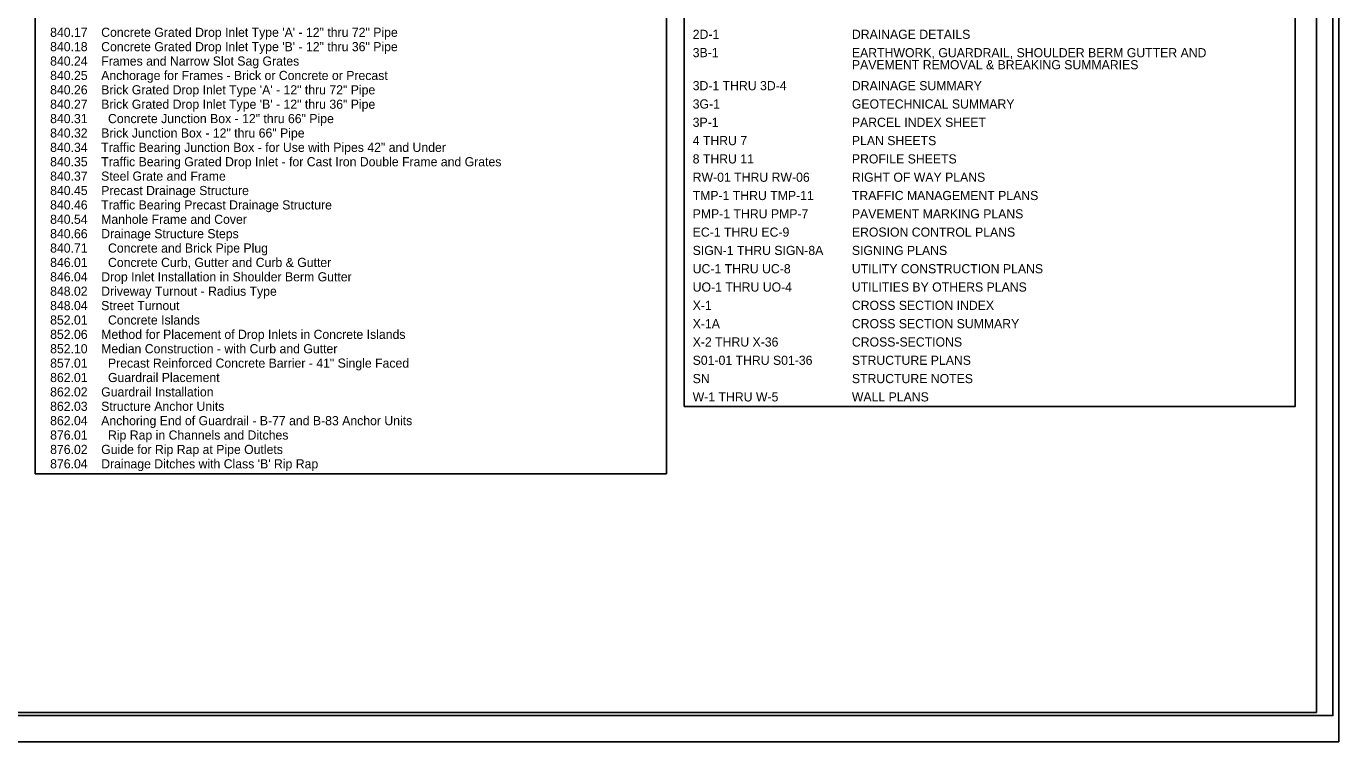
# Model space of a CAD drawing. Extents: x 93723152 to 93807327, y 70087853 to 70142603.
# Drawn here: x 93757166 to 93807327, y 70087853 to 70115212 of the extents above; entities that cross this region are included whole.
import ezdxf

# ---------------------------------------------------------------- set-up
doc = ezdxf.new("R2010")
doc.units = 0
for name, color, linetype in [('Default', 7, 'Continuous'), ('Old_Level_1', 7, 'Continuous'), ('Sheet Cutting Line CELL', 7, 'Continuous'), ('Sheet Plan CELL', 7, 'Continuous'), ('Sheet Plot Border Inside CELL', 7, 'Continuous'), ('Sheet Plot Border Outside CELL', 7, 'Continuous')]:
    doc.layers.add(name, color=color, linetype=linetype)

msp = doc.modelspace()

# ---------------------------------------------------------------- linework, layer by layer
at = {"layer": 'Old_Level_1'}
for points in [[(93757503, 70098101), (93781631, 70098101), (93781631, 70138611), (93757503, 70138611)], [(93782306, 70100674), (93805663, 70100674), (93805663, 70125470), (93782306, 70125470)]]:
    msp.add_lwpolyline(points, close=True, dxfattribs=at)
at = {"layer": 'Sheet Cutting Line CELL'}
msp.add_line((93723152, 70087853), (93807327, 70087853), dxfattribs=at)
at = {"layer": 'Sheet Plan CELL'}
for points in [[(93731477, 70088977), (93731476, 70141476), (93796475, 70141478), (93796476, 70133975), (93806477, 70133974), (93806477, 70088977)], [(93806477, 70141478), (93731477, 70141478), (93731477, 70088978), (93806477, 70088978)]]:
    msp.add_lwpolyline(points, close=True, dxfattribs=at)
at = {"layer": 'Sheet Plot Border Inside CELL'}
msp.add_lwpolyline([(93723802, 70088853), (93807102, 70088853), (93807102, 70141603), (93723802, 70141603)], close=True, dxfattribs=at)
at = {"layer": 'Sheet Plot Border Outside CELL'}
msp.add_lwpolyline([(93723152, 70087853), (93807327, 70087853), (93807327, 70142603), (93723152, 70142603)], close=True, dxfattribs=at)

# ---------------------------------------------------------------- texts
at = {"layer": 'Default'}
for s, p in [('840.17    Concrete Grated Drop Inlet Type \'A\' - 12" thru 72" Pipe', (93758079, 70114806)), ('840.18    Concrete Grated Drop Inlet Type \'B\' - 12" thru 36" Pipe', (93758079, 70114256)), ('840.26    Brick Grated Drop Inlet Type \'A\' - 12" thru 72" Pipe', (93758079, 70112606)), ('840.27    Brick Grated Drop Inlet Type \'B\' - 12" thru 36" Pipe', (93758079, 70112056)), ('840.31      Concrete Junction Box - 12" thru 66" Pipe', (93758079, 70111506)), ('840.32    Brick Junction Box - 12" thru 66" Pipe', (93758079, 70110956)), ('840.34    Traffic Bearing Junction Box - for Use with Pipes 42" and Under', (93758079, 70110406)), ('840.35    Traffic Bearing Grated Drop Inlet - for Cast Iron Double Frame and Grates', (93758079, 70109856)), ('840.54    Manhole Frame and Cover', (93758079, 70107656))]:
    msp.add_text(s, height=350, dxfattribs=at).set_placement(p)
at = {"layer": 'Old_Level_1'}
for s, p in [('2D-1 ', (93782637, 70114729)), ('DRAINAGE DETAILS', (93788722, 70114729)), ('3B-1    ', (93782637, 70114029)), ('EARTHWORK, GUARDRAIL, SHOULDER BERM GUTTER AND ', (93788722, 70114025)), ('840.24    Frames and Narrow Slot Sag Grates', (93758079, 70113706)), ('PAVEMENT REMOVAL & BREAKING SUMMARIES', (93788722, 70113566)), ('840.25    Anchorage for Frames - Brick or Concrete or Precast', (93758079, 70113156)), ('3D-1 THRU 3D-4    ', (93782636, 70112765)), ('DRAINAGE SUMMARY', (93788720, 70112765)), ('3G-1', (93782636, 70112065)), ('GEOTECHNICAL SUMMARY', (93788720, 70112065)), ('3P-1     ', (93782636, 70111365)), ('PARCEL INDEX SHEET', (93788720, 70111365)), ('4 THRU 7    ', (93782636, 70110665)), ('PLAN SHEETS', (93788720, 70110665)), ('8 THRU 11', (93782636, 70109965)), ('PROFILE SHEETS', (93788720, 70109965)), ('840.37    Steel Grate and Frame', (93758079, 70109306)), ('RW-01 THRU RW-06', (93782636, 70109265)), ('RIGHT OF WAY PLANS', (93788720, 70109265)), ('840.45    Precast Drainage Structure', (93758079, 70108756)), ('TMP-1 THRU TMP-11    ', (93782636, 70108565)), ('TRAFFIC MANAGEMENT PLANS', (93788720, 70108565)), ('840.46    Traffic Bearing Precast Drainage Structure', (93758079, 70108206)), ('PMP-1 THRU PMP-7   ', (93782636, 70107865)), ('PAVEMENT MARKING PLANS', (93788720, 70107865)), ('840.66    Drainage Structure Steps', (93758079, 70107106)), ('EC-1 THRU EC-9     ', (93782636, 70107165)), ('EROSION CONTROL PLANS', (93788720, 70107165)), ('840.71      Concrete and Brick Pipe Plug', (93758079, 70106556)), ('SIGN-1 THRU SIGN-8A     ', (93782636, 70106465)), ('SIGNING PLANS', (93788720, 70106465)), ('846.01      Concrete Curb, Gutter and Curb & Gutter', (93758079, 70106006)), ('846.04    Drop Inlet Installation in Shoulder Berm Gutter', (93758079, 70105456)), ('UC-1 THRU UC-8     ', (93782636, 70105765)), ('UTILITY CONSTRUCTION PLANS', (93788720, 70105765)), ('848.02    Driveway Turnout - Radius Type', (93758079, 70104906)), ('UO-1 THRU UO-4    ', (93782636, 70105065)), ('UTILITIES BY OTHERS PLANS', (93788720, 70105065)), ('848.04    Street Turnout', (93758079, 70104356)), ('X-1', (93782636, 70104365)), ('CROSS SECTION INDEX', (93788720, 70104365)), ('852.01      Concrete Islands', (93758079, 70103806)), ('X-1A', (93782636, 70103665)), ('CROSS SECTION SUMMARY', (93788720, 70103665)), ('852.06    Method for Placement of Drop Inlets in Concrete Islands', (93758079, 70103256)), ('X-2 THRU X-36', (93782636, 70102965)), ('CROSS-SECTIONS', (93788720, 70102965)), ('852.10    Median Construction - with Curb and Gutter', (93758079, 70102706)), ('857.01      Precast Reinforced Concrete Barrier - 41" Single Faced', (93758079, 70102156)), ('S01-01 THRU S01-36', (93782636, 70102265)), ('STRUCTURE PLANS', (93788720, 70102265)), ('862.01      Guardrail Placement', (93758079, 70101606)), ('SN', (93782636, 70101565)), ('STRUCTURE NOTES', (93788720, 70101565)), ('862.02    Guardrail Installation', (93758079, 70101056)), ('W-1 THRU W-5', (93782636, 70100865)), ('WALL PLANS', (93788720, 70100865)), ('862.03    Structure Anchor Units', (93758079, 70100506)), ('862.04    Anchoring End of Guardrail - B-77 and B-83 Anchor Units', (93758079, 70099956)), ('876.01      Rip Rap in Channels and Ditches', (93758079, 70099406)), ('876.02    Guide for Rip Rap at Pipe Outlets', (93758079, 70098856)), ("876.04    Drainage Ditches with Class 'B' Rip Rap", (93758079, 70098306))]:
    msp.add_text(s, height=350, dxfattribs=at).set_placement(p)

doc.saveas('drawing.dxf')
